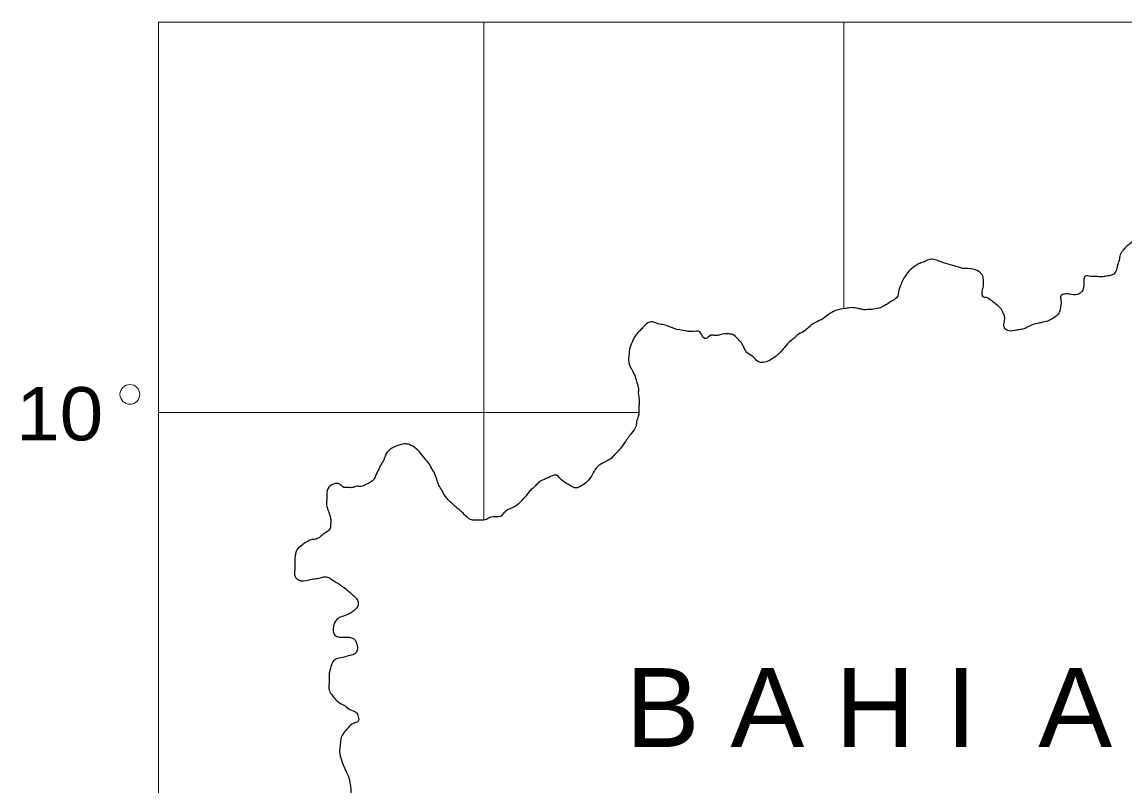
# Model space of a CAD drawing. Extents: x 854879 to 917879, y 8541948 to 8631048.
# Drawn here: x 902515 to 909782, y 8555944 to 8560979 of the extents above; entities that cross this region are included whole.
import ezdxf
from ezdxf.enums import TextEntityAlignment as Align

# ---------------------------------------------------------------- set-up
doc = ezdxf.new("R2010")
doc.units = 0
doc.header["$LTSCALE"] = 160
doc.layers.add('63', color=7, linetype='Continuous', lineweight=13)

msp = doc.modelspace()

# ---------------------------------------------------------------- linework, layer by layer
at = {"layer": '63'}
for p, q in [((905557.6, 8560979), (905557.6, 8557696.9)), ((907928.9, 8560979), (907928.9, 8559089.1)), ((903413.8, 8558404.9), (906578.1, 8558404.9))]:
    msp.add_line(p, q, dxfattribs=at)
msp.add_lwpolyline([(912712.9, 8560979), (903413.8, 8560979), (903413.8, 8550908.8), (912712.9, 8550908.8)], close=True, dxfattribs=at)
msp.add_circle((903225.5, 8558524.8), 65.1, dxfattribs=at)
at = {"layer": '63', "lineweight": 25}
for points in [[(910471.7, 8559350), (910423, 8559371.5), (910387, 8559379.4), (910334.6, 8559391.1), (910295.3, 8559395.8), (910256.3, 8559420.2), (910237.2, 8559447.2), (910205, 8559474.8), (910169.6, 8559509.1), (910150.4, 8559532.9), (910124.4, 8559543.7), (910101.6, 8559557.6), (910072.1, 8559562), (910029.6, 8559570.1), (909954.2, 8559579.3), (909914.6, 8559570.8), (909878.2, 8559562.2), (909844.9, 8559543.4), (909814.8, 8559518.1), (909791.3, 8559499.1), (909771.2, 8559476.8), (909750.8, 8559444.4), (909743.3, 8559408.4), (909732.8, 8559375.8), (909722, 8559336.5), (909701.9, 8559314), (909668.8, 8559305.3), (909635.8, 8559299.8), (909586.6, 8559301.5), (909553.7, 8559302.7), (909520.9, 8559303.9), (909510.4, 8559274.5), (909509.3, 8559231.6), (909492.2, 8559195.8), (909468.9, 8559183.5), (909419.6, 8559185.2), (909386.8, 8559186.3), (909360.2, 8559174), (909359.7, 8559147.6), (909355, 8559085.1), (909341.1, 8559052.6), (909314.3, 8559030.3), (909281.1, 8559011.8), (909241.4, 8558999.9), (909214.9, 8558994.2), (909175.4, 8558985.6), (909138.7, 8558967.2), (909108.9, 8558954.9), (909075.9, 8558949.5), (909046.3, 8558943.9), (909010.1, 8558945.2), (908987.5, 8558962.5), (908988.4, 8559008.6), (908989.1, 8559035), (908979.7, 8559061.8), (908960.7, 8559095.5), (908931.8, 8559119.5), (908909.1, 8559136.9), (908873.5, 8559161.2), (908847.4, 8559168.8), (908841.7, 8559205.2), (908848.9, 8559238.1), (908849.6, 8559271), (908843.9, 8559307.5), (908811.6, 8559338.3), (908749.5, 8559353.8), (908713.3, 8559354.9), (908687.2, 8559362.5), (908648.1, 8559373.8), (908586.1, 8559392.4), (908556.7, 8559403.3), (908520.8, 8559414.5), (908487.9, 8559412.3), (908454.7, 8559396.9), (908421.5, 8559385), (908398.2, 8559369.2), (908354.7, 8559334.4), (908341, 8559311.8), (908324.1, 8559289.3), (908306.8, 8559250.3), (908289.3, 8559198), (908282, 8559168.5), (908251.8, 8559143.2), (908222, 8559124.5), (908191.9, 8559105.6), (908162, 8559093.5), (908115.9, 8559085.2), (908076.3, 8559083.2), (908050.1, 8559084.2), (908024, 8559091.7), (907978.1, 8559096.6)], [(910471.7, 8559350), (910423, 8559371.5), (910387, 8559379.4), (910334.6, 8559391.1), (910295.3, 8559395.8), (910256.3, 8559420.2), (910237.2, 8559447.2), (910205, 8559474.8), (910169.6, 8559509.1), (910150.4, 8559532.9), (910124.4, 8559543.7), (910101.6, 8559557.6), (910072.1, 8559562), (910029.6, 8559570.1), (909954.2, 8559579.3), (909914.6, 8559570.8), (909878.2, 8559562.2), (909844.9, 8559543.4), (909814.8, 8559518.1), (909791.3, 8559499.1), (909771.2, 8559476.8), (909750.8, 8559444.4), (909743.3, 8559408.4), (909732.8, 8559375.8), (909722, 8559336.5), (909701.9, 8559314), (909668.8, 8559305.3), (909635.8, 8559299.8), (909586.6, 8559301.5), (909553.7, 8559302.7), (909520.9, 8559303.9), (909510.4, 8559274.5), (909509.3, 8559231.6), (909492.2, 8559195.8), (909468.9, 8559183.5), (909419.6, 8559185.2), (909386.8, 8559186.3), (909360.2, 8559174), (909359.7, 8559147.6), (909355, 8559085.1), (909341.1, 8559052.6), (909314.3, 8559030.3), (909281.1, 8559011.8), (909241.4, 8558999.9), (909214.9, 8558994.2), (909175.4, 8558985.6), (909138.7, 8558967.2), (909108.9, 8558954.9), (909075.9, 8558949.5), (909046.3, 8558943.9), (909010.1, 8558945.2), (908987.5, 8558962.5), (908988.4, 8559008.6), (908989.1, 8559035), (908979.7, 8559061.8), (908960.7, 8559095.5), (908931.8, 8559119.5), (908909.1, 8559136.9), (908873.5, 8559161.2), (908847.4, 8559168.8), (908841.7, 8559205.2), (908848.9, 8559238.1), (908849.6, 8559271), (908843.9, 8559307.5), (908811.6, 8559338.3), (908749.5, 8559353.8), (908713.3, 8559354.9), (908687.2, 8559362.5), (908648.1, 8559373.8), (908586.1, 8559392.4), (908556.7, 8559403.3), (908520.8, 8559414.5), (908487.9, 8559412.3), (908454.7, 8559396.9), (908421.5, 8559385), (908398.2, 8559369.2), (908354.7, 8559334.4), (908341, 8559311.8), (908324.1, 8559289.3), (908306.8, 8559250.3), (908289.3, 8559198), (908282, 8559168.5), (908251.8, 8559143.2), (908222, 8559124.5), (908191.9, 8559105.6), (908162, 8559093.5), (908115.9, 8559085.2), (908076.3, 8559083.2), (908050.1, 8559084.2), (908024, 8559091.7), (907978.1, 8559096.6)], [(907978.1, 8559096.6), (907941.8, 8559091.3), (907875.8, 8559077), (907825.8, 8559049.1), (907792.4, 8559023.8), (907742.5, 8558999.1), (907712.6, 8558980.4), (907692.5, 8558961.3), (907659.1, 8558936), (907625.8, 8558917.4), (907605.6, 8558898.3), (907582.1, 8558879.3), (907538.4, 8558834.6), (907491.3, 8558783.3), (907461.2, 8558761.2), (907427.9, 8558742.7), (907388.4, 8558734.1), (907362.3, 8558741.6), (907333.3, 8558772.3), (907291.2, 8558800.2), (907269.1, 8558840.5), (907249.9, 8558871), (907230.7, 8558891.5), (907198.5, 8558918.9), (907172.2, 8558923.2), (907142.7, 8558924.3), (907083.3, 8558913.1), (907053.8, 8558914.1), (907020.4, 8558892.2), (906997.7, 8558909.4), (906981.9, 8558936.3), (906919.5, 8558938.6), (906886.7, 8558943), (906811.5, 8558958.8), (906743.1, 8558984.3), (906706.9, 8558988.9), (906658.1, 8559003.8), (906621.4, 8558982), (906597.7, 8558956.4), (906577.7, 8558937.3), (906554.1, 8558908.4), (906540.3, 8558882.4), (906519.5, 8558830.3), (906515.4, 8558800.8), (906511.4, 8558764.6), (906514, 8558731.5), (906532.7, 8558687.9), (906554.7, 8558640.9), (906566.9, 8558600.8), (906576, 8558560.9), (906575.4, 8558531.3), (906581, 8558491.4), (906580.4, 8558465), (906579.9, 8558438.6), (906575.2, 8558379.4), (906564.6, 8558343.4), (906560.8, 8558317.2), (906530.1, 8558268.7), (906486.1, 8558207.4), (906455.5, 8558165.6), (906428.6, 8558136.8), (906398.3, 8558104.9), (906361.7, 8558083), (906328.4, 8558064.4), (906305, 8558045.5), (906281.3, 8558013.2), (906260.8, 8557977.6), (906237.1, 8557948.7), (906203.7, 8557923.5), (906163.9, 8557908.3), (906128.2, 8557922.7), (906102.2, 8557936.9), (906060.2, 8557971.4), (906037.6, 8557991.9), (905997.9, 8557983.4), (905964.8, 8557968.1), (905931.6, 8557952.8), (905908.1, 8557933.8), (905887.9, 8557911.3), (905864.5, 8557892.3), (905844.2, 8557866.6), (905810.5, 8557828.2), (905773.5, 8557793.1), (905740.2, 8557774.5), (905710.5, 8557762.3), (905690.3, 8557743.2), (905666.8, 8557720.8), (905604.3, 8557716.4), (905574.4, 8557701), (905541.3, 8557695.5), (905508.5, 8557696.7)], [(907978.1, 8559096.6), (907941.8, 8559091.3), (907875.8, 8559077), (907825.8, 8559049.1), (907792.4, 8559023.8), (907742.5, 8558999.1), (907712.6, 8558980.4), (907692.5, 8558961.3), (907659.1, 8558936), (907625.8, 8558917.4), (907605.6, 8558898.3), (907582.1, 8558879.3), (907538.4, 8558834.6), (907491.3, 8558783.3), (907461.2, 8558761.2), (907427.9, 8558742.7), (907388.4, 8558734.1), (907362.3, 8558741.6), (907333.3, 8558772.3), (907291.2, 8558800.2), (907269.1, 8558840.5), (907249.9, 8558871), (907230.7, 8558891.5), (907198.5, 8558918.9), (907172.2, 8558923.2), (907142.7, 8558924.3), (907083.3, 8558913.1), (907053.8, 8558914.1), (907020.4, 8558892.2), (906997.7, 8558909.4), (906981.9, 8558936.3), (906919.5, 8558938.6), (906886.7, 8558943), (906811.5, 8558958.8), (906743.1, 8558984.3), (906706.9, 8558988.9), (906658.1, 8559003.8), (906621.4, 8558982), (906597.7, 8558956.4), (906577.7, 8558937.3), (906554.1, 8558908.4), (906540.3, 8558882.4), (906519.5, 8558830.3), (906515.4, 8558800.8), (906511.4, 8558764.6), (906514, 8558731.5), (906532.7, 8558687.9), (906554.7, 8558640.9), (906566.9, 8558600.8), (906576, 8558560.9), (906575.4, 8558531.3), (906581, 8558491.4), (906580.4, 8558465), (906579.9, 8558438.6), (906575.2, 8558379.4), (906564.6, 8558343.4), (906560.8, 8558317.2), (906530.1, 8558268.7), (906486.1, 8558207.4), (906455.5, 8558165.6), (906428.6, 8558136.8), (906398.3, 8558104.9), (906361.7, 8558083), (906328.4, 8558064.4), (906305, 8558045.5), (906281.3, 8558013.2), (906260.8, 8557977.6), (906237.1, 8557948.7), (906203.7, 8557923.5), (906163.9, 8557908.3), (906128.2, 8557922.7), (906102.2, 8557936.9), (906060.2, 8557971.4), (906037.6, 8557991.9), (905997.9, 8557983.4), (905964.8, 8557968.1), (905931.6, 8557952.8), (905908.1, 8557933.8), (905887.9, 8557911.3), (905864.5, 8557892.3), (905844.2, 8557866.6), (905810.5, 8557828.2), (905773.5, 8557793.1), (905740.2, 8557774.5), (905710.5, 8557762.3), (905690.3, 8557743.2), (905666.8, 8557720.8), (905604.3, 8557716.4), (905574.4, 8557701), (905541.3, 8557695.5), (905508.5, 8557696.7)], [(905508.5, 8557696.7), (905475.7, 8557697.8), (905440.1, 8557722.2), (905401.5, 8557759.8), (905375.6, 8557780.5), (905353, 8557801.2), (905327.2, 8557825.1), (905304.9, 8557852.3), (905289, 8557879.3), (905266.8, 8557916.4), (905251.2, 8557953.3), (905235.7, 8558000), (905220, 8558027), (905197.8, 8558067.3), (905169, 8558101.4), (905133.8, 8558145.6), (905104.8, 8558173), (905075.6, 8558190.4), (905042.9, 8558198.2), (905006.7, 8558192.9), (904976.9, 8558184), (904943.6, 8558165.3), (904920.1, 8558143.1), (904895.9, 8558087.7), (904882.2, 8558065.1), (904865.1, 8558032.7), (904844.4, 8557987.2), (904830.6, 8557961.2), (904804, 8557942.4), (904780.7, 8557930), (904747.6, 8557917.9), (904721.3, 8557918.8), (904688.2, 8557910.1), (904661.9, 8557911), (904635.6, 8557911.9), (904609.8, 8557932.6), (904567.1, 8557934.1), (904530.2, 8557902.3), (904522.5, 8557853.1), (904521.9, 8557823.4), (904521.2, 8557793.8), (904530.5, 8557763.6), (904542.8, 8557727), (904548.8, 8557700.3), (904548.2, 8557670.7), (904544.2, 8557641), (904504.1, 8557606.2), (904477.3, 8557584), (904454, 8557571.6), (904421, 8557566.2), (904387.7, 8557550.7), (904361.1, 8557531.8), (904327.5, 8557503.4), (904313.1, 8557441.1), (904312.3, 8557404.8), (904311.6, 8557371.8), (904310.8, 8557335.5), (904336.2, 8557301.6), (904405.3, 8557302.5), (904435.1, 8557308.1), (904471.3, 8557313.4), (904504.3, 8557322.1), (904533.8, 8557317.8), (904556.6, 8557303.8), (904608.5, 8557272.3), (904631.1, 8557255.1), (904663.5, 8557230.9), (904686, 8557210.2), (904711.7, 8557186.2), (904727.7, 8557162.5), (904726.9, 8557129.6), (904703.2, 8557100.6), (904676.6, 8557081.8), (904633.4, 8557063.4), (904597, 8557048.2), (904569.7, 8557006.2), (904565.7, 8556973.3), (904571.7, 8556943.4), (904597.6, 8556926), (904627.2, 8556925), (904669.8, 8556923.6), (904705.7, 8556909.1), (904721.4, 8556878.8), (904723.9, 8556839.2), (904710.3, 8556816.4), (904677.1, 8556804.5), (904637.3, 8556792.7), (904594.4, 8556784.2), (904567.8, 8556768.6), (904554.1, 8556742.7), (904539.8, 8556693.7)], [(905508.5, 8557696.7), (905475.7, 8557697.8), (905440.1, 8557722.2), (905401.5, 8557759.8), (905375.6, 8557780.5), (905353, 8557801.2), (905327.2, 8557825.1), (905304.9, 8557852.3), (905289, 8557879.3), (905266.8, 8557916.4), (905251.2, 8557953.3), (905235.7, 8558000), (905220, 8558027), (905197.8, 8558067.3), (905169, 8558101.4), (905133.8, 8558145.6), (905104.8, 8558173), (905075.6, 8558190.4), (905042.9, 8558198.2), (905006.7, 8558192.9), (904976.9, 8558184), (904943.6, 8558165.3), (904920.1, 8558143.1), (904895.9, 8558087.7), (904882.2, 8558065.1), (904865.1, 8558032.7), (904844.4, 8557987.2), (904830.6, 8557961.2), (904804, 8557942.4), (904780.7, 8557930), (904747.6, 8557917.9), (904721.3, 8557918.8), (904688.2, 8557910.1), (904661.9, 8557911), (904635.6, 8557911.9), (904609.8, 8557932.6), (904567.1, 8557934.1), (904530.2, 8557902.3), (904522.5, 8557853.1), (904521.9, 8557823.4), (904521.2, 8557793.8), (904530.5, 8557763.6), (904542.8, 8557727), (904548.8, 8557700.3), (904548.2, 8557670.7), (904544.2, 8557641), (904504.1, 8557606.2), (904477.3, 8557584), (904454, 8557571.6), (904421, 8557566.2), (904387.7, 8557550.7), (904361.1, 8557531.8), (904327.5, 8557503.4), (904313.1, 8557441.1), (904312.3, 8557404.8), (904311.6, 8557371.8), (904310.8, 8557335.5), (904336.2, 8557301.6), (904405.3, 8557302.5), (904435.1, 8557308.1), (904471.3, 8557313.4), (904504.3, 8557322.1), (904533.8, 8557317.8), (904556.6, 8557303.8), (904608.5, 8557272.3), (904631.1, 8557255.1), (904663.5, 8557230.9), (904686, 8557210.2), (904711.7, 8557186.2), (904727.7, 8557162.5), (904726.9, 8557129.6), (904703.2, 8557100.6), (904676.6, 8557081.8), (904633.4, 8557063.4), (904597, 8557048.2), (904569.7, 8557006.2), (904565.7, 8556973.3), (904571.7, 8556943.4), (904597.6, 8556926), (904627.2, 8556925), (904669.8, 8556923.6), (904705.7, 8556909.1), (904721.4, 8556878.8), (904723.9, 8556839.2), (904710.3, 8556816.4), (904677.1, 8556804.5), (904637.3, 8556792.7), (904594.4, 8556784.2), (904567.8, 8556768.6), (904554.1, 8556742.7), (904539.8, 8556693.7)], [(904539.8, 8556693.7), (904539.3, 8556667.2), (904538.3, 8556621.1), (904537.5, 8556581.5), (904553.1, 8556548), (904572.3, 8556524.2), (904594.8, 8556500.3), (904643.4, 8556472.2), (904675.8, 8556447.9), (904714.9, 8556430.1), (904730.7, 8556399.8), (904730, 8556370.2), (904700.1, 8556357.9), (904663.3, 8556326.2), (904632.9, 8556291), (904615.6, 8556252), (904611.7, 8556219.1), (904607.3, 8556172.9), (904622.4, 8556106.4), (904641, 8556059.6), (904653.6, 8556032.7), (904669.2, 8555995.9), (904675, 8555962.6), (904680.9, 8555926.1), (904679.8, 8555883.2), (904672, 8555824), (904651.1, 8555772), (904640.3, 8555726.1), (904639.7, 8555699.7), (904652, 8555662.9), (904671.1, 8555632.7), (904676.8, 8555592.8), (904640.1, 8555567.7), (904613.2, 8555535.6), (904589.4, 8555503.4), (904582.2, 8555477.2), (904581.4, 8555437.7), (904587.2, 8555404.4), (904596.5, 8555377.7), (904595.7, 8555344.7), (904575.3, 8555312.3), (904574.8, 8555285.9), (904583.8, 8555249.3), (904628.2, 8555178.4), (904660.7, 8555157.5), (904703, 8555136.3), (904732.1, 8555115.4), (904768.2, 8555114.2), (904794.2, 8555100.1), (904809.7, 8555059.9), (904828.8, 8555029.6), (904847.3, 8554972.8), (904869.1, 8554922.5), (904871.8, 8554895.9), (904881.1, 8554865.9), (904886.9, 8554832.8), (904892.7, 8554792.9), (904895, 8554753.2), (904893.7, 8554690.6), (904885.9, 8554634.7), (904875.1, 8554592.1), (904864.4, 8554559.5), (904856.6, 8554503.6), (904846, 8554464.3), (904832.1, 8554431.8), (904824.9, 8554402.3), (904821, 8554376.1), (904807.4, 8554350.2), (904800, 8554314.1), (904789.4, 8554281.4), (904785.5, 8554255.2), (904814.9, 8554247.5), (904841.8, 8554273), (904865.1, 8554285.5), (904894.9, 8554294.3), (904925.2, 8554326.3), (904948.7, 8554351.9), (904978.7, 8554370.6), (905008.9, 8554396), (905038.9, 8554418.1), (905068.7, 8554426.9), (905098.7, 8554445.8), (905168.4, 8554476.3), (905234.6, 8554497.1), (905281, 8554515.3), (905310.6, 8554520.9), (905343.9, 8554539.5), (905380.5, 8554558.1), (905416.9, 8554573.3), (905450.2, 8554592), (905477, 8554614.1)], [(904539.8, 8556693.7), (904539.3, 8556667.2), (904538.3, 8556621.1), (904537.5, 8556581.5), (904553.1, 8556548), (904572.3, 8556524.2), (904594.8, 8556500.3), (904643.4, 8556472.2), (904675.8, 8556447.9), (904714.9, 8556430.1), (904730.7, 8556399.8), (904730, 8556370.2), (904700.1, 8556357.9), (904663.3, 8556326.2), (904632.9, 8556291), (904615.6, 8556252), (904611.7, 8556219.1), (904607.3, 8556172.9), (904622.4, 8556106.4), (904641, 8556059.6), (904653.6, 8556032.7), (904669.2, 8555995.9), (904675, 8555962.6), (904680.9, 8555926.1), (904679.8, 8555883.2), (904672, 8555824), (904651.1, 8555772), (904640.3, 8555726.1), (904639.7, 8555699.7), (904652, 8555662.9), (904671.1, 8555632.7), (904676.8, 8555592.8), (904640.1, 8555567.7), (904613.2, 8555535.6), (904589.4, 8555503.4), (904582.2, 8555477.2), (904581.4, 8555437.7), (904587.2, 8555404.4), (904596.5, 8555377.7), (904595.7, 8555344.7), (904575.3, 8555312.3), (904574.8, 8555285.9), (904583.8, 8555249.3), (904628.2, 8555178.4), (904660.7, 8555157.5), (904703, 8555136.3), (904732.1, 8555115.4), (904768.2, 8555114.2), (904794.2, 8555100.1), (904809.7, 8555059.9), (904828.8, 8555029.6), (904847.3, 8554972.8), (904869.1, 8554922.5), (904871.8, 8554895.9), (904881.1, 8554865.9), (904886.9, 8554832.8), (904892.7, 8554792.9), (904895, 8554753.2), (904893.7, 8554690.6), (904885.9, 8554634.7), (904875.1, 8554592.1), (904864.4, 8554559.5), (904856.6, 8554503.6), (904846, 8554464.3), (904832.1, 8554431.8), (904824.9, 8554402.3), (904821, 8554376.1), (904807.4, 8554350.2), (904800, 8554314.1), (904789.4, 8554281.4), (904785.5, 8554255.2), (904814.9, 8554247.5), (904841.8, 8554273), (904865.1, 8554285.5), (904894.9, 8554294.3), (904925.2, 8554326.3), (904948.7, 8554351.9), (904978.7, 8554370.6), (905008.9, 8554396), (905038.9, 8554418.1), (905068.7, 8554426.9), (905098.7, 8554445.8), (905168.4, 8554476.3), (905234.6, 8554497.1), (905281, 8554515.3), (905310.6, 8554520.9), (905343.9, 8554539.5), (905380.5, 8554558.1), (905416.9, 8554573.3), (905450.2, 8554592), (905477, 8554614.1)]]:
    msp.add_spline(points, degree=3, dxfattribs=at)

# ---------------------------------------------------------------- texts
at = {"layer": '63'}
for s, height, width, p in [('10', 351, 1.1, (903050.1, 8558221.6)), ('B A H I  A', 520, 1.05, (909698, 8556200.8))]:
    msp.add_text(s, height=height, dxfattribs=dict(at, width=width)).set_placement(p, align=Align.RIGHT)

doc.saveas('drawing.dxf')
